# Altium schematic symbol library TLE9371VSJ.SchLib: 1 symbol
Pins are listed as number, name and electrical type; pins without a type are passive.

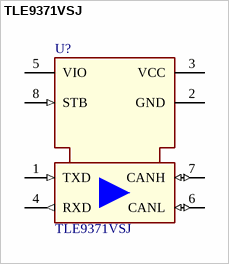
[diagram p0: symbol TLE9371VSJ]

## TLE9371VSJ
designator U?
High Speed CAN Transceiver; Manufacturer: Infineon Technologies
pins: 1 TXD (in) "Transmit Data Input", 2 GND (power) "Ground", 3 VCC (power) "Transmitter Supply Voltage", 4 RXD (out) "Receive Data Output", 5 VIO (power) "Digital Supply Voltage", 6 CANL (io) "CAN Bus Low Level I/O", 7 CANH (io) "CAN Bus High Level I/O", 8 STB (in) "Stand-by Input"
